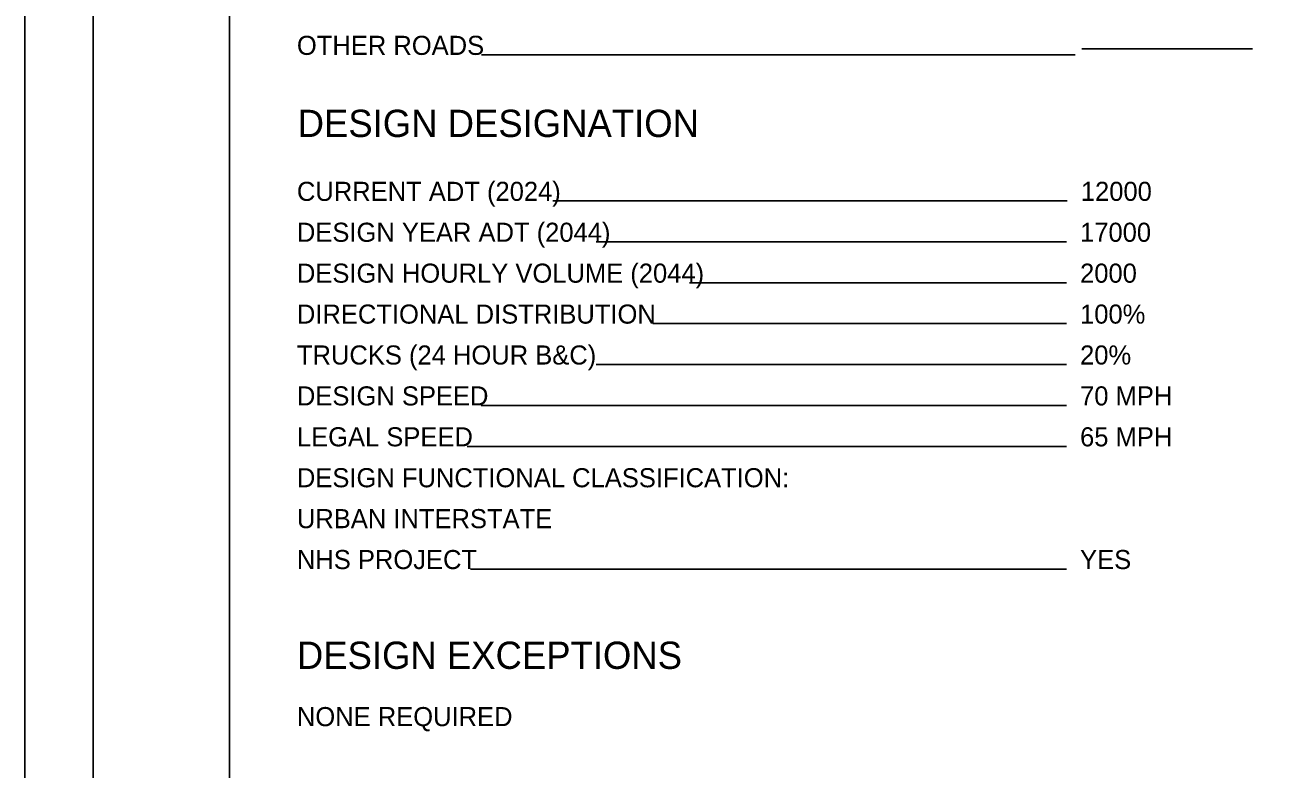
# Model space of a CAD drawing. Extents: x -5.6 to 34, y 0 to 22.
# Drawn here: x 0 to 9.13, y 5.64 to 11.1 of the extents above; entities that cross this region are included whole.
import ezdxf

# ---------------------------------------------------------------- set-up
doc = ezdxf.new("R2010")
doc.units = 0
for name, color, linetype in [('SH_Border', 7, 'Continuous'), ('SH_Cut_Line', 7, 'Continuous'), ('SH_Data', 7, 'Continuous'), ('SH_Text', 7, 'Continuous')]:
    doc.layers.add(name, color=color, linetype=linetype)

msp = doc.modelspace()

# ---------------------------------------------------------------- linework, layer by layer
at = {"layer": 'SH_Border'}
for points in [[(0.5, 21.5), (1.5, 21.5), (1.5, 0.5), (0.5, 0.5)], [(1.5, 21.5), (33.5, 21.5), (33.5, 0.5), (1.5, 0.5)]]:
    msp.add_lwpolyline(points, close=True, dxfattribs=at)
at = {"layer": 'SH_Cut_Line'}
msp.add_lwpolyline([(0, 0), (34, 0), (34, 22), (0, 22)], close=True, dxfattribs=at)
at = {"layer": 'SH_Data'}
for p, q in [((7.7, 10.8767), (3.3471, 10.8767)), ((9, 10.9223), (7.75, 10.9223)), ((7.6424, 9.8062), (3.871, 9.8062)), ((7.6368, 9.5062), (4.1885, 9.5062)), ((7.6368, 9.2062), (4.8723, 9.2062)), ((7.6368, 8.9062), (4.6037, 8.9062)), ((7.6368, 8.6062), (4.1885, 8.6062)), ((7.6368, 8.3062), (3.346, 8.3062)), ((7.6368, 8.0062), (3.2422, 8.0062)), ((7.6368, 7.1062), (3.2669, 7.1062))]:
    msp.add_line(p, q, dxfattribs=at)

# ---------------------------------------------------------------- texts
msp.add_text('DESIGN DESIGNATION', height=0.2, dxfattribs=at).set_placement((2, 10.2747))
at = {"layer": 'SH_Text'}
for s, height, p in [('OTHER ROADS', 0.14, (1.9944, 10.8767)), ('CURRENT ADT (2024)', 0.14, (1.9944, 9.8062)), ('12000', 0.14, (7.7424, 9.8062)), ('DESIGN YEAR ADT (2044)', 0.14, (1.9944, 9.5062)), ('17000', 0.14, (7.7368, 9.5062)), ('DESIGN HOURLY VOLUME (2044)', 0.14, (1.9944, 9.2062)), ('2000', 0.14, (7.7368, 9.2062)), ('DIRECTIONAL DISTRIBUTION', 0.14, (1.9944, 8.9062)), ('100%', 0.14, (7.7368, 8.9062)), ('TRUCKS (24 HOUR B&C)', 0.14, (1.9944, 8.6062)), ('20%', 0.14, (7.7368, 8.6062)), ('DESIGN SPEED', 0.14, (1.9944, 8.3062)), ('70 MPH', 0.14, (7.7368, 8.3062)), ('LEGAL SPEED', 0.14, (1.9944, 8.0062)), ('65 MPH', 0.14, (7.7368, 8.0062)), ('DESIGN FUNCTIONAL CLASSIFICATION:', 0.14, (1.9944, 7.7062)), ('URBAN INTERSTATE', 0.14, (1.9944, 7.4062)), ('NHS PROJECT', 0.14, (1.9944, 7.1062)), ('YES', 0.14, (7.7368, 7.1062)), ('DESIGN EXCEPTIONS', 0.2, (1.9944, 6.3744)), ('NONE REQUIRED', 0.14, (1.9944, 5.9544))]:
    msp.add_text(s, height=height, dxfattribs=at).set_placement(p)

doc.saveas('drawing.dxf')
